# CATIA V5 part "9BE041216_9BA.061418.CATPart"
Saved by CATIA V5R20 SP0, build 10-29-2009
Part number: 9BE041216_9BA.061418
Revision: ANY
Definition: UNKNOWN
Nomenclature: 9BE041216_9BA.061418
Source: Unknown
Bounding box of the stored display mesh (mm): x -8 to 8, y 0 to 25.5, z -8 to 8
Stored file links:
  C:\Users\Utente\Desktop\IO LAVORO\3D X SITO CF\CUMSA\3D files BE\BE 041216\9BE041216_9BA.061418.CATPart
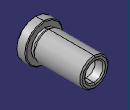
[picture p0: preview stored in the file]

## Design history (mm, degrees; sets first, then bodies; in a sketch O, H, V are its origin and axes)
Body1 "Chaflán4" (main body)
  Solid1: solid without history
